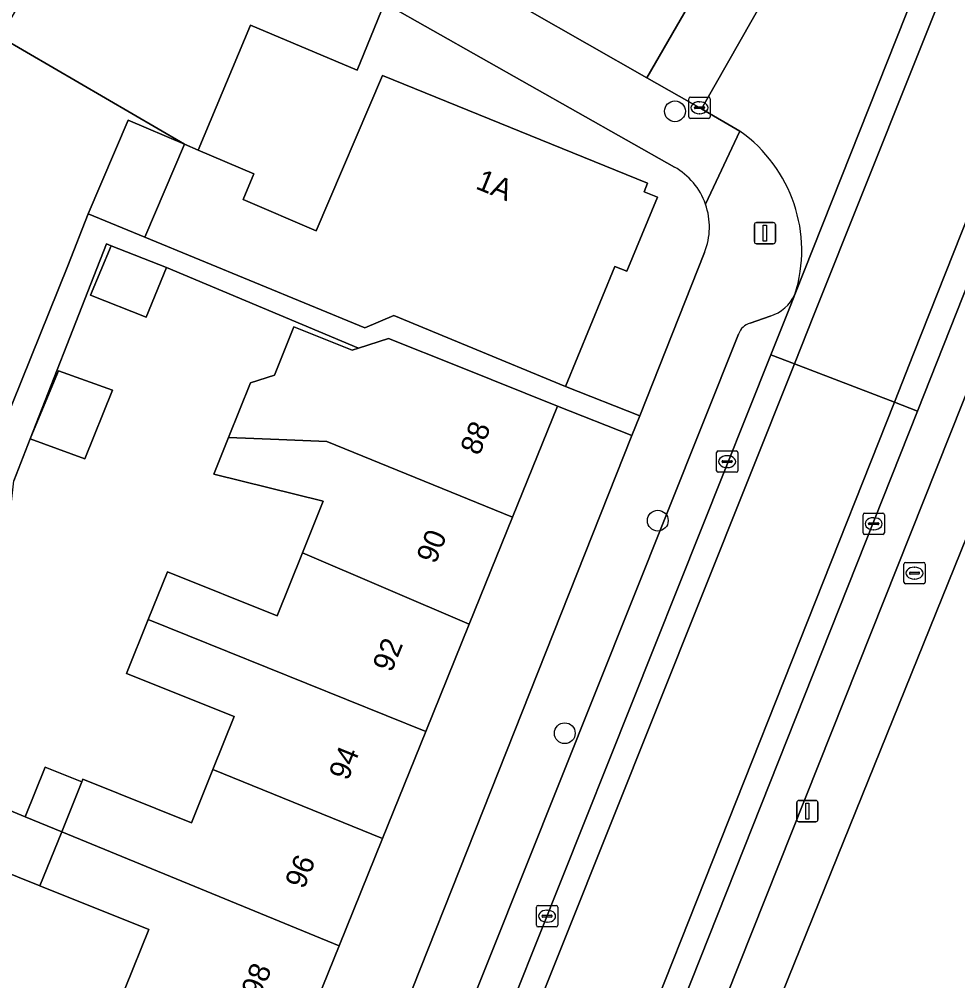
# Model space of a CAD drawing. Extents: x 160023 to 161302, y 384750 to 385707.
# Drawn here: x 160407.81 to 160451.93, y 385019.84 to 385065.04 of the extents above; entities that cross this region are included whole.
import ezdxf

# ---------------------------------------------------------------- set-up
doc = ezdxf.new("R2010")
doc.units = 0
for name, color, linetype in [('IMGEO_Boom', 7, 'Continuous'), ('IMGEO_Brandkraan', 7, 'Continuous'), ('IMGEO_Erf', 7, 'Continuous'), ('IMGEO_Kolk', 7, 'Continuous'), ('IMGEO_Lichtmast', 7, 'Continuous'), ('IMGEO_Pand', 7, 'Continuous'), ('IMGEO_Pand_nummerreeks', 7, 'Continuous'), ('IMGEO_Parkeervlak_open', 7, 'Continuous'), ('IMGEO_Rijbaan_lokaal_gesloten', 7, 'Continuous'), ('IMGEO_Rijbaan_lokaal_open', 7, 'Continuous'), ('IMGEO_Voetpad_open', 7, 'Continuous')]:
    doc.layers.add(name, color=color, linetype=linetype)

msp = doc.modelspace()

# ---------------------------------------------------------------- linework, layer by layer
at = {"layer": 'IMGEO_Boom'}
for centre in [(160438.633, 385060.712), (160437.827, 385041.468), (160433.453, 385031.473)]:
    msp.add_circle(centre, 0.489, dxfattribs=at)
at = {"layer": 'IMGEO_Brandkraan'}
for p, q in [((160449.393, 385038.573), (160449.393, 385039.425)), ((160449.468, 385039.499), (160450.32, 385039.499)), ((160449.881, 385039.279), (160449.906, 385039.279)), ((160450.394, 385039.425), (160450.394, 385038.573)), ((160449.652, 385038.993), (160449.652, 385039.005)), ((160450.09, 385038.956), (160449.692, 385038.956)), ((160449.695, 385039.042), (160450.093, 385039.042)), ((160449.904, 385038.719), (160449.879, 385038.719)), ((160450.136, 385039.005), (160450.136, 385038.993)), ((160450.32, 385038.499), (160449.468, 385038.499))]:
    msp.add_line(p, q, dxfattribs=at)
for points in [[(160449.393, 385038.573), (160449.393, 385039.425)], [(160449.468, 385039.499), (160450.32, 385039.499)], [(160450.394, 385039.425), (160450.394, 385038.573)], [(160450.32, 385038.499), (160449.468, 385038.499)]]:
    msp.add_lwpolyline(points, dxfattribs=at)
for centre, radius, start, end in [((160449.47, 385039.423), 0.0765, 91.552, 178.448), ((160449.47, 385039.423), 0.0765, 91.552, 178.448), ((160450.318, 385039.423), 0.0765, 1.552, 88.448), ((160450.318, 385039.423), 0.0765, 1.552, 88.448), ((160449.692, 385039.002), 0.0403, 85.8775, 175.7526), ((160449.689, 385038.992), 0.0366, 178.938, 274.7102), ((160450.093, 385038.999), 0.043, 264.8664, 352.4533), ((160450.097, 385039.004), 0.0386, 1.7309, 96.639), ((160449.47, 385038.575), 0.0765, 181.552, 268.448), ((160449.47, 385038.575), 0.0765, 181.552, 268.448), ((160450.318, 385038.575), 0.0765, 271.552, 358.448), ((160450.318, 385038.575), 0.0765, 271.552, 358.448)]:
    msp.add_arc(centre, radius, start, end, dxfattribs=at)
for centre, major_axis, ratio, start_param, end_param in [((160449.88, 385038.999), (-0.387, 0.002), 0.722429, 4.712389, 7.853982), ((160449.905, 385038.999), (-0.39, 0.002), 0.717154, 1.570796, 4.712389)]:
    msp.add_ellipse(centre, major_axis=major_axis, ratio=ratio, start_param=start_param, end_param=end_param, dxfattribs=at)
at = {"layer": 'IMGEO_Erf'}
for points in [[(160438.609, 385058.093), (160424.98, 385065.798), (160423.699, 385062.643), (160418.68, 385064.766), (160416.228, 385058.883), (160418.844, 385057.768), (160418.33, 385056.562), (160421.77, 385055.094), (160424.883, 385062.397)], [(160405.728, 385042.636), (160410.094, 385053.443), (160411.055, 385055.898), (160412.927, 385060.29), (160415.579, 385059.16), (160406.899, 385064.215)], [(160424.883, 385062.397), (160437.345, 385057.328), (160437.192, 385056.925), (160437.809, 385056.671), (160436.374, 385053.189), (160435.815, 385053.42), (160433.49, 385047.781), (160436.98, 385046.397), (160440.026, 385054.075)], [(160545.057, 385054.237), (160536.066, 385055.512), (160527.327, 385056.456), (160503.68, 385057.663), (160500, 385057.851), (160467.624, 385059.507), (160467.516, 385057.578), (160465.833, 385057.662), (160460.997, 385057.904), (160458.726, 385056.493), (160441.331, 385013.476)], [(160405.435, 385028.633), (160408.092, 385027.542), (160409.028, 385029.872), (160410.746, 385029.182), (160410.8, 385029.316), (160415.903, 385027.267), (160416.909, 385029.771), (160417.908, 385032.259), (160412.857, 385034.287), (160413.874, 385036.82), (160414.773, 385039.058), (160419.934, 385036.985), (160421.126, 385039.953), (160422.105, 385042.39), (160416.96, 385043.658), (160417.651, 385045.377), (160418.682, 385047.944), (160419.805, 385048.306), (160420.72, 385050.585), (160423.461, 385049.484), (160423.761, 385049.581), (160414.726, 385053.374), (160413.77, 385051.028), (160411.166, 385052.072), (160412.137, 385054.388), (160411.907, 385054.478), (160411.315, 385052.965), (160408.319, 385045.311), (160407.556, 385043.347)], [(160418.576, 385000), (160436.61, 385045.463), (160433.107, 385046.853), (160430.996, 385041.631), (160428.965, 385036.607), (160426.924, 385031.554), (160424.892, 385026.528), (160422.854, 385021.485), (160420.753, 385016.287)], [(160412.788, 385019.485), (160413.898, 385022.249), (160408.787, 385024.302), (160404.571, 385025.995)]]:
    msp.add_lwpolyline(points, dxfattribs=at)
msp.add_lwpolyline([(160408.319, 385045.311), (160409.661, 385048.509), (160412.199, 385047.599), (160410.891, 385044.367)], close=True, dxfattribs=at)
for centre, radius, start, end in [((160437.005, 385055.265), 3.251, 19.4736, 60.4342), ((160437.013, 385055.271), 3.241, 338.3528, 19.4303)]:
    msp.add_arc(centre, radius, start, end, dxfattribs=at)
at = {"layer": 'IMGEO_Kolk'}
for p, q in [((160439.286, 385060.454), (160439.286, 385061.306)), ((160439.361, 385061.38), (160440.213, 385061.38)), ((160440.287, 385061.306), (160440.287, 385060.454)), ((160439.545, 385060.874), (160439.545, 385060.886)), ((160439.588, 385060.923), (160439.986, 385060.923)), ((160439.774, 385061.16), (160439.799, 385061.16)), ((160440.029, 385060.886), (160440.029, 385060.874)), ((160439.983, 385060.837), (160439.585, 385060.837)), ((160439.797, 385060.6), (160439.772, 385060.6)), ((160440.213, 385060.38), (160439.361, 385060.38)), ((160440.587, 385043.817), (160440.587, 385044.669)), ((160440.662, 385044.743), (160441.514, 385044.743)), ((160441.588, 385044.669), (160441.588, 385043.817)), ((160440.846, 385044.237), (160440.846, 385044.249)), ((160441.284, 385044.2), (160440.886, 385044.2)), ((160440.889, 385044.286), (160441.287, 385044.286)), ((160441.075, 385044.523), (160441.1, 385044.523)), ((160441.33, 385044.249), (160441.33, 385044.237)), ((160441.514, 385043.743), (160440.662, 385043.743)), ((160441.098, 385043.963), (160441.073, 385043.963)), ((160447.475, 385040.896), (160447.475, 385041.748)), ((160447.55, 385041.822), (160448.402, 385041.822)), ((160447.963, 385041.602), (160447.988, 385041.602)), ((160448.476, 385041.748), (160448.476, 385040.896)), ((160447.734, 385041.316), (160447.734, 385041.328)), ((160448.172, 385041.279), (160447.774, 385041.279)), ((160447.777, 385041.365), (160448.175, 385041.365)), ((160447.986, 385041.042), (160447.961, 385041.042)), ((160448.218, 385041.328), (160448.218, 385041.316)), ((160448.402, 385040.822), (160447.55, 385040.822)), ((160432.198, 385023.373), (160433.05, 385023.373)), ((160432.123, 385022.447), (160432.123, 385023.299)), ((160432.382, 385022.867), (160432.382, 385022.879)), ((160432.425, 385022.916), (160432.823, 385022.916)), ((160432.611, 385023.153), (160432.636, 385023.153)), ((160432.866, 385022.879), (160432.866, 385022.867)), ((160433.124, 385023.299), (160433.124, 385022.447)), ((160432.82, 385022.83), (160432.422, 385022.83)), ((160432.634, 385022.593), (160432.609, 385022.593)), ((160433.05, 385022.373), (160432.198, 385022.373))]:
    msp.add_line(p, q, dxfattribs=at)
for points in [[(160439.286, 385060.454), (160439.286, 385061.306)], [(160439.361, 385061.38), (160440.213, 385061.38)], [(160440.287, 385061.306), (160440.287, 385060.454)], [(160440.213, 385060.38), (160439.361, 385060.38)], [(160440.587, 385043.817), (160440.587, 385044.669)], [(160440.662, 385044.743), (160441.514, 385044.743)], [(160441.588, 385044.669), (160441.588, 385043.817)], [(160441.514, 385043.743), (160440.662, 385043.743)], [(160447.475, 385040.896), (160447.475, 385041.748)], [(160447.55, 385041.822), (160448.402, 385041.822)], [(160448.476, 385041.748), (160448.476, 385040.896)], [(160448.402, 385040.822), (160447.55, 385040.822)], [(160432.198, 385023.373), (160433.05, 385023.373)], [(160432.123, 385022.447), (160432.123, 385023.299)], [(160433.124, 385023.299), (160433.124, 385022.447)], [(160433.05, 385022.373), (160432.198, 385022.373)]]:
    msp.add_lwpolyline(points, dxfattribs=at)
for centre, radius, start, end in [((160439.363, 385061.304), 0.0765, 91.552, 178.448), ((160439.363, 385061.304), 0.0765, 91.552, 178.448), ((160440.211, 385061.304), 0.0765, 1.552, 88.448), ((160440.211, 385061.304), 0.0765, 1.552, 88.448), ((160439.585, 385060.883), 0.0403, 85.8775, 175.7526), ((160439.582, 385060.873), 0.0366, 178.938, 274.7102), ((160439.986, 385060.88), 0.043, 264.8664, 352.4533), ((160439.99, 385060.885), 0.0386, 1.7309, 96.639), ((160439.363, 385060.456), 0.0765, 181.552, 268.448), ((160439.363, 385060.456), 0.0765, 181.552, 268.448), ((160440.211, 385060.456), 0.0765, 271.552, 358.448), ((160440.211, 385060.456), 0.0765, 271.552, 358.448), ((160440.664, 385044.667), 0.0765, 91.552, 178.448), ((160440.664, 385044.667), 0.0765, 91.552, 178.448), ((160441.512, 385044.667), 0.0765, 1.552, 88.448), ((160441.512, 385044.667), 0.0765, 1.552, 88.448), ((160440.886, 385044.246), 0.0403, 85.8775, 175.7526), ((160440.883, 385044.236), 0.0366, 178.938, 274.7102), ((160441.287, 385044.243), 0.043, 264.8664, 352.4533), ((160441.291, 385044.248), 0.0386, 1.7309, 96.639), ((160440.664, 385043.819), 0.0765, 181.552, 268.448), ((160440.664, 385043.819), 0.0765, 181.552, 268.448), ((160441.512, 385043.819), 0.0765, 271.552, 358.448), ((160441.512, 385043.819), 0.0765, 271.552, 358.448), ((160447.552, 385041.746), 0.0765, 91.552, 178.448), ((160447.552, 385041.746), 0.0765, 91.552, 178.448), ((160448.4, 385041.746), 0.0765, 1.552, 88.448), ((160448.4, 385041.746), 0.0765, 1.552, 88.448), ((160447.774, 385041.325), 0.0403, 85.8775, 175.7526), ((160447.771, 385041.315), 0.0366, 178.938, 274.7102), ((160448.175, 385041.322), 0.043, 264.8664, 352.4533), ((160448.179, 385041.327), 0.0386, 1.7309, 96.639), ((160447.552, 385040.898), 0.0765, 181.552, 268.448), ((160447.552, 385040.898), 0.0765, 181.552, 268.448), ((160448.4, 385040.898), 0.0765, 271.552, 358.448), ((160448.4, 385040.898), 0.0765, 271.552, 358.448), ((160432.2, 385023.297), 0.0765, 91.552, 178.448), ((160432.2, 385023.297), 0.0765, 91.552, 178.448), ((160433.048, 385023.297), 0.0765, 1.552, 88.448), ((160433.048, 385023.297), 0.0765, 1.552, 88.448), ((160432.422, 385022.876), 0.0403, 85.8775, 175.7526), ((160432.827, 385022.878), 0.0386, 1.7309, 96.639), ((160432.2, 385022.449), 0.0765, 181.552, 268.448), ((160432.2, 385022.449), 0.0765, 181.552, 268.448), ((160432.419, 385022.866), 0.0366, 178.938, 274.7102), ((160432.823, 385022.873), 0.043, 264.8664, 352.4533), ((160433.048, 385022.449), 0.0765, 271.552, 358.448), ((160433.048, 385022.449), 0.0765, 271.552, 358.448)]:
    msp.add_arc(centre, radius, start, end, dxfattribs=at)
for centre, major_axis, ratio, start_param, end_param in [((160439.773, 385060.88), (-0.387, 0.002), 0.722429, 4.712389, 7.853982), ((160439.798, 385060.88), (-0.39, 0.002), 0.717154, 1.570796, 4.712389), ((160441.074, 385044.243), (-0.387, 0.002), 0.722429, 4.712389, 7.853982), ((160441.099, 385044.243), (-0.39, 0.002), 0.717154, 1.570796, 4.712389), ((160447.962, 385041.322), (-0.387, 0.002), 0.722429, 4.712389, 7.853982), ((160447.987, 385041.322), (-0.39, 0.002), 0.717154, 1.570796, 4.712389), ((160432.61, 385022.873), (-0.387, 0.002), 0.722429, 4.712389, 7.853982), ((160432.635, 385022.873), (-0.39, 0.002), 0.717154, 1.570796, 4.712389)]:
    msp.add_ellipse(centre, major_axis=major_axis, ratio=ratio, start_param=start_param, end_param=end_param, dxfattribs=at)
at = {"layer": 'IMGEO_Lichtmast'}
for p, q in [((160442.466, 385055.484), (160443.256, 385055.484)), ((160443.256, 385055.484), (160442.466, 385055.484)), ((160442.366, 385054.584), (160442.366, 385055.384)), ((160442.366, 385055.384), (160442.366, 385054.584)), ((160443.356, 385055.384), (160443.356, 385054.584)), ((160443.356, 385054.584), (160443.356, 385055.384)), ((160443.256, 385054.484), (160442.466, 385054.484)), ((160442.466, 385054.484), (160443.256, 385054.484)), ((160444.46, 385028.313), (160445.25, 385028.313)), ((160445.25, 385028.313), (160444.46, 385028.313)), ((160444.36, 385027.413), (160444.36, 385028.213)), ((160444.36, 385028.213), (160444.36, 385027.413)), ((160445.35, 385028.213), (160445.35, 385027.413)), ((160445.35, 385027.413), (160445.35, 385028.213)), ((160445.25, 385027.313), (160444.46, 385027.313)), ((160444.46, 385027.313), (160445.25, 385027.313))]:
    msp.add_line(p, q, dxfattribs=at)
for points in [[(160442.786, 385055.359), (160442.936, 385055.359), (160442.936, 385054.609), (160442.786, 385054.609), (160442.786, 385055.359)], [(160444.78, 385028.188), (160444.93, 385028.188), (160444.93, 385027.438), (160444.78, 385027.438), (160444.78, 385028.188)]]:
    msp.add_lwpolyline(points, dxfattribs=at)
for centre, start, end in [((160442.466, 385055.384), 90, 180), ((160442.466, 385055.384), 90, 180), ((160443.256, 385055.384), 0, 90), ((160443.256, 385055.384), 360, 90), ((160442.466, 385054.584), 180, 270), ((160442.466, 385054.584), 180, 270), ((160443.256, 385054.584), 270, 0), ((160443.256, 385054.584), 270, 0), ((160444.46, 385028.213), 90, 180), ((160444.46, 385028.213), 90, 180), ((160445.25, 385028.213), 0, 90), ((160445.25, 385028.213), 360, 90), ((160444.46, 385027.413), 180, 270), ((160444.46, 385027.413), 180, 270), ((160445.25, 385027.413), 270, 0), ((160445.25, 385027.413), 270, 0)]:
    msp.add_arc(centre, 0.1, start, end, dxfattribs=at)
at = {"layer": 'IMGEO_Pand'}
for points in [[(160413.72, 385054.8), (160424.058, 385050.538), (160425.423, 385051.106), (160428.868, 385049.686), (160433.49, 385047.781), (160435.815, 385053.42), (160436.374, 385053.189), (160437.809, 385056.671), (160437.192, 385056.925), (160437.345, 385057.328), (160424.883, 385062.397), (160421.77, 385055.094), (160418.33, 385056.562), (160418.844, 385057.768), (160416.228, 385058.883), (160415.579, 385059.16)], [(160415.579, 385059.16), (160412.927, 385060.29), (160411.055, 385055.898), (160413.72, 385054.8)], [(160414.726, 385053.374), (160412.137, 385054.388), (160411.166, 385052.072), (160413.77, 385051.028)], [(160428.468, 385048.716), (160425.176, 385050.037), (160423.761, 385049.581), (160423.461, 385049.484), (160420.72, 385050.585), (160419.805, 385048.306), (160418.682, 385047.944), (160417.651, 385045.377), (160418.837, 385045.332), (160420.011, 385045.289), (160422.262, 385045.192), (160430.996, 385041.631), (160433.107, 385046.853)], [(160409.661, 385048.509), (160408.319, 385045.311), (160410.891, 385044.367), (160412.199, 385047.599)], [(160417.651, 385045.377), (160416.96, 385043.658), (160422.105, 385042.39), (160421.126, 385039.953), (160428.965, 385036.607), (160430.996, 385041.631), (160422.262, 385045.192), (160420.011, 385045.289), (160418.837, 385045.332)], [(160426.924, 385031.554), (160428.965, 385036.607), (160421.126, 385039.953), (160419.934, 385036.985), (160414.773, 385039.058), (160413.874, 385036.82)], [(160413.874, 385036.82), (160412.857, 385034.287), (160417.908, 385032.259), (160416.909, 385029.771), (160424.892, 385026.528), (160426.924, 385031.554)], [(160410.746, 385029.182), (160409.028, 385029.872), (160408.092, 385027.542), (160409.806, 385026.839)], [(160416.909, 385029.771), (160415.903, 385027.267), (160410.8, 385029.316), (160410.746, 385029.182), (160409.806, 385026.839), (160422.854, 385021.485), (160424.892, 385026.528)], [(160408.092, 385027.542), (160405.435, 385028.633), (160404.403, 385026.063), (160404.571, 385025.995), (160408.787, 385024.302), (160409.806, 385026.839)], [(160409.806, 385026.839), (160408.787, 385024.302), (160413.898, 385022.249), (160412.788, 385019.485), (160416.114, 385018.15), (160420.753, 385016.287), (160422.854, 385021.485)]]:
    msp.add_lwpolyline(points, close=True, dxfattribs=at)
at = {"layer": 'IMGEO_Parkeervlak_open'}
msp.add_lwpolyline([(160418.68, 385064.766), (160423.699, 385062.643), (160424.98, 385065.798), (160412.003, 385072.979), (160411.517, 385072.145), (160406.899, 385064.215), (160415.579, 385059.16), (160416.228, 385058.883)], close=True, dxfattribs=at)
for points in [[(160455.854, 385061.298), (160450.033, 385046.622), (160437.787, 385015.747)], [(160440.413, 385017.495), (160456.521, 385057.978)], [(160423.495, 385000), (160443.146, 385049.264), (160444.082, 385051.611), (160444.275, 385052.096)], [(160443.116, 385051.088), (160442.167, 385050.759)], [(160441.621, 385050.24), (160421.572, 385000), (160394.613, 384932.443), (160392.369, 384926.82), (160387.031, 384913.444)]]:
    msp.add_lwpolyline(points, dxfattribs=at)
for centre, radius, start, end in [((160442.564, 385052.893), 1.887, 286.9982, 335.0298), ((160442.414, 385049.953), 0.843, 107.0231, 160.0724)]:
    msp.add_arc(centre, radius, start, end, dxfattribs=at)
at = {"layer": 'IMGEO_Rijbaan_lokaal_gesloten'}
msp.add_lwpolyline([(160428.901, 385067.092), (160437.316, 385062.291), (160441.257, 385069.142)], dxfattribs=at)
at = {"layer": 'IMGEO_Rijbaan_lokaal_open'}
for points in [[(160456.884, 385080.495), (160456.95, 385080.661), (160455.778, 385081.134), (160455.177, 385079.664), (160451.665, 385070.767), (160451.564, 385070.512), (160451.217, 385069.636), (160444.275, 385052.096), (160444.082, 385051.611), (160443.146, 385049.264), (160444.248, 385048.841), (160445.179, 385051.173)], [(160461.163, 385077.845), (160461.545, 385078.805), (160456.95, 385080.661), (160456.884, 385080.495), (160445.179, 385051.173), (160444.248, 385048.841), (160448.949, 385047.038), (160449.849, 385049.309)], [(160462.221, 385077.395), (160462.611, 385078.375), (160461.545, 385078.805), (160461.163, 385077.845), (160449.849, 385049.309), (160448.949, 385047.038), (160450.033, 385046.622), (160455.854, 385061.298)], [(160424.752, 385000), (160444.248, 385048.841), (160443.146, 385049.264), (160423.495, 385000), (160387.693, 384910.244), (160386.94, 384907.618), (160386.194, 384904.906), (160384.663, 384899.459), (160384.45, 384898.732), (160384.332, 384898.414), (160385.418, 384898), (160385.618, 384898.566), (160388.819, 384909.958)], [(160430.241, 385000), (160436.681, 385016.096), (160448.949, 385047.038), (160444.248, 385048.841), (160424.752, 385000), (160388.819, 384909.958), (160385.618, 384898.566), (160385.418, 384898), (160388.913, 384896.667)]]:
    msp.add_lwpolyline(points, close=True, dxfattribs=at)
for points in [[(160444.275, 385052.096), (160451.217, 385069.636)], [(160441.637, 385068.931), (160441.441, 385069.04), (160441.257, 385069.142), (160437.316, 385062.291), (160439.877, 385060.829), (160442.902, 385066.151)], [(160442.902, 385066.151), (160439.877, 385060.829), (160441.689, 385059.774)], [(160431.47, 385000), (160434.346, 385007.194), (160434.727, 385008.141), (160437.516, 385015.078), (160437.787, 385015.747), (160450.033, 385046.622), (160448.949, 385047.038), (160436.681, 385016.096), (160430.241, 385000), (160388.913, 384896.667), (160386.013, 384889.416), (160385.258, 384887.528)]]:
    msp.add_lwpolyline(points, dxfattribs=at)
msp.add_arc((160437.723, 385054.164), 6.871, 342.4862, 54.7415, dxfattribs=at)
at = {"layer": 'IMGEO_Voetpad_open'}
for points in [[(160359.363, 385104.964), (160360.355, 385101.627), (160373.936, 385093.737), (160393.395, 385082.624), (160411.517, 385072.145), (160412.003, 385072.979), (160424.98, 385065.798), (160438.609, 385058.093)], [(160440.07, 385056.349), (160441.689, 385059.774), (160439.877, 385060.829), (160437.316, 385062.291), (160428.901, 385067.092), (160424.416, 385069.645), (160418.139, 385073.218)], [(160441.689, 385059.774), (160440.07, 385056.349)], [(160456.521, 385057.978), (160440.413, 385017.495)], [(160437.787, 385015.747), (160437.516, 385015.078), (160441.331, 385013.476), (160458.726, 385056.493)], [(160440.026, 385054.075), (160436.98, 385046.397), (160436.61, 385045.463), (160418.576, 385000), (160386.007, 384917.894), (160379.738, 384902.09), (160376.921, 384903.209), (160374.691, 384897.666), (160377.472, 384896.55), (160375.717, 384892.348), (160372.439, 384884.099), (160364.181, 384863.317)], [(160442.167, 385050.759), (160443.116, 385051.088)], [(160387.031, 384913.444), (160392.369, 384926.82), (160391.905, 384927.005), (160394.149, 384932.628), (160394.613, 384932.443), (160421.572, 385000), (160441.621, 385050.24)]]:
    msp.add_lwpolyline(points, dxfattribs=at)
msp.add_lwpolyline([(160428.868, 385049.686), (160425.423, 385051.106), (160424.058, 385050.538), (160413.72, 385054.8), (160411.055, 385055.898), (160410.094, 385053.443), (160405.728, 385042.636), (160405.167, 385034.621), (160405.134, 385034.157), (160406.478, 385033.791), (160406.567, 385034.575), (160407.556, 385043.347), (160408.319, 385045.311), (160411.315, 385052.965), (160411.907, 385054.478), (160412.137, 385054.388), (160414.726, 385053.374), (160423.761, 385049.581), (160425.176, 385050.037), (160428.468, 385048.716), (160433.107, 385046.853), (160436.61, 385045.463), (160436.98, 385046.397), (160433.49, 385047.781)], close=True, dxfattribs=at)
for centre, radius, start, end in [((160437.723, 385054.164), 6.871, 342.4862, 54.7415), ((160437.005, 385055.265), 3.251, 19.4736, 60.4342), ((160437.013, 385055.271), 3.241, 338.3528, 19.4303), ((160442.564, 385052.893), 1.887, 286.9982, 335.0298), ((160442.414, 385049.953), 0.843, 107.0231, 160.0724)]:
    msp.add_arc(centre, radius, start, end, dxfattribs=at)

# ---------------------------------------------------------------- texts
at = {"layer": 'IMGEO_Pand_nummerreeks'}
for s, rotation, p in [('1A', 337.8656, (160429.217, 385057.093)), ('88', 67.9929, (160429.433, 385044.487)), ('90', 67.9929, (160427.374, 385039.392)), ('92', 67.9927, (160425.312, 385034.293)), ('94', 67.9927, (160423.255, 385029.201)), ('96', 67.9929, (160421.196, 385024.106)), ('98', 67.9927, (160419.138, 385019.015))]:
    msp.add_text(s, height=1, rotation=rotation, dxfattribs=at).set_placement(p)

doc.saveas('drawing.dxf')
